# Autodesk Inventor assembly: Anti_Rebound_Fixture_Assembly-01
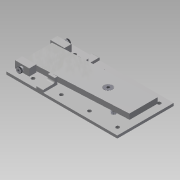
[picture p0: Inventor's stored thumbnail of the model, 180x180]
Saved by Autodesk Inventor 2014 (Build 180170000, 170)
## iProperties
Company: NHTSA/VRTC
Created: 2012-08
Part Number: Anti_Rebound_Fixture_Assembly-01
Document SubType Name: Weldment
Designer: Mike Vanvoorhis
Weld Material: Welded Steel Mild
Mass: 12341 g
Surface Area: 3135.86 cm^2
Volume: 1591.33 cm^3
Density: 7.75514 g/cm^3
Description: ANTI-REBOUND FIXTURE ASS'Y.
Project: CHILD SIDE IMPACT SLED
DESIGN DATE: 2012-11-05
Author: Dave Walker
Title: Anti-Rebound Fixture Assembly
Subject: Child Side Impact Sled
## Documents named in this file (12)
- B:\VRTC_DWG\BIO\Non-P572\Child Side-Frontal Impact Sled\Side Impact Sled\Anti_Rebound_Fixture_Assembly.iam
- B:\VRTC_DWG\BIO\Non-P572\Child Side-Frontal Impact Sled\Side Impact Sled\Anti_Rebound_Fixture_Base.ipt
- B:\VRTC_DWG\BIO\Non-P572\Child Side-Frontal Impact Sled\Side Impact Sled\Anti_Rebound_Fixture_Pivot.ipt
- B:\VRTC_DWG\BIO\Non-P572\Child Side-Frontal Impact Sled\Side Impact Sled\Anti_Rebound_Fixture_Stop.ipt
- B:\VRTC_DWG\BIO\Non-P572\Child Side-Frontal Impact Sled\Side Impact Sled\Anti_Rebound_Fixture_Shoulder Bolt.ipt
- B:\VRTC_DWG\BIO\Non-P572\Child Side-Frontal Impact Sled\Side Impact Sled\Anti_Rebound_Fixture_Guide.ipt
- B:\VRTC_DWG\BIO\Non-P572\Child Side-Frontal Impact Sled\Side Impact Sled\Anti_Rebound_Fixture_Spring.ipt
- B:\VRTC_DWG\BIO\Non-P572\Child Side-Frontal Impact Sled\Side Impact Sled\90630A130.ipt
- B:\VRTC_DWG\BIO\Non-P572\Child Side-Frontal Impact Sled\Side Impact Sled\Rubber_Washer.ipt
- B:\VRTC_DWG\Inventor Support Files\Content Center\en-US\ASTM F436(1)\ASTM F436 - 5_8(1).ipt
- B:\VRTC_DWG\Inventor Support Files\Content Center\en-US\ANSI B18.3(04)\ANSI B18.3 - 5_8-11 UNC - 3.5(30).ipt
- Anti_Rebound_Fixture_Assembly-01.iam
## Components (16 placed, 10 different names)
1. Anti_Rebound_Fixture_Base:1 — Flush:1, Flush:2, Flush:3, Flush:4, Mate:1, Flush:5, Flush:6, Flush:8, Insert:9, Flush:10, Flush:11, Flush:12, Insert:20, Insert:22, Insert:23
2. Anti_Rebound_Fixture_Pivot:1 — Flush:1, Insert:12, Insert:13, Flush:10, Flush:12
3. Anti_Rebound_Fixture_Pivot:2 — Flush:2, Flush:3, Mate:2, Flush:9, Flush:11
4. Anti_Rebound_Fixture_Stop:1 — Insert:12, Tangent:1, Mate:3, Mate:4
5. Anti_Rebound_Fixture_Shoulder Bolt:1 — Insert:13
6. Anti_Rebound_Fixture_Shoulder Bolt:2 — Mate:2, Flush:9
7. Anti_Rebound_Fixture_Guide:1 — Flush:4, Mate:1, Flush:7, Flush:8
8. Anti_Rebound_Fixture_Guide:2 — Flush:5, Flush:6, Flush:7
9. Anti_Rebound_Fixture_Spring:1 — Insert:22, Tangent:1
10. Anti_Rebound_Fixture_Spring:2 — Insert:9
11. Anti_Rebound_Fixture_Spring:3 — Insert:23
12. Anti_Rebound_Fixture_Spring:5 — Insert:20
13. 90630A130:1 — Insert:18
14. Rubber_Washer:1 — Insert:19, Insert:24
15. Socket Flat Countersunk Head Cap Screw - Inch 5/8-11 UNC x 3.5 — Mate:3, Mate:4, Insert:24
16. Circular Washer (Inch) 5/8:1 — Insert:18, Insert:19
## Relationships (26: Flush 12, Insert 9, Mate 4, Tangent 1)
- Flush:1: Anti_Rebound_Fixture_Base:1 ↔ Anti_Rebound_Fixture_Pivot:1
- Flush:2: Anti_Rebound_Fixture_Base:1 ↔ Anti_Rebound_Fixture_Pivot:2
- Flush:3: Anti_Rebound_Fixture_Base:1 ↔ Anti_Rebound_Fixture_Pivot:2
- Flush:4: Anti_Rebound_Fixture_Base:1 ↔ Anti_Rebound_Fixture_Guide:1
- Mate:1: Anti_Rebound_Fixture_Base:1 ↔ Anti_Rebound_Fixture_Guide:1
- Flush:5: Anti_Rebound_Fixture_Base:1 ↔ Anti_Rebound_Fixture_Guide:2
- Flush:6: Anti_Rebound_Fixture_Base:1 ↔ Anti_Rebound_Fixture_Guide:2
- Flush:7: Anti_Rebound_Fixture_Guide:1 ↔ Anti_Rebound_Fixture_Guide:2
- Flush:8: Anti_Rebound_Fixture_Base:1 ↔ Anti_Rebound_Fixture_Guide:1
- Insert:9: Anti_Rebound_Fixture_Base:1 ↔ Anti_Rebound_Fixture_Spring:2
- Insert:12: Anti_Rebound_Fixture_Pivot:1 ↔ Anti_Rebound_Fixture_Stop:1
- Insert:13: Anti_Rebound_Fixture_Pivot:1 ↔ Anti_Rebound_Fixture_Shoulder Bolt:1
- Mate:2: Anti_Rebound_Fixture_Pivot:2 ↔ Anti_Rebound_Fixture_Shoulder Bolt:2
- Flush:9: Anti_Rebound_Fixture_Pivot:2 ↔ Anti_Rebound_Fixture_Shoulder Bolt:2
- Flush:10: Anti_Rebound_Fixture_Base:1 ↔ Anti_Rebound_Fixture_Pivot:1
- Flush:11: Anti_Rebound_Fixture_Base:1 ↔ Anti_Rebound_Fixture_Pivot:2
- Flush:12: Anti_Rebound_Fixture_Base:1 ↔ Anti_Rebound_Fixture_Pivot:1
- Insert:18: 90630A130:1 ↔ Circular Washer (Inch) 5/8:1
- Insert:19: Rubber_Washer:1 ↔ Circular Washer (Inch) 5/8:1
- Insert:20: Anti_Rebound_Fixture_Base:1 ↔ Anti_Rebound_Fixture_Spring:5
- Insert:22: Anti_Rebound_Fixture_Base:1 ↔ Anti_Rebound_Fixture_Spring:1
- Insert:23: Anti_Rebound_Fixture_Base:1 ↔ Anti_Rebound_Fixture_Spring:3
- Tangent:1: Anti_Rebound_Fixture_Stop:1 ↔ Anti_Rebound_Fixture_Spring:1
- Mate:3: Anti_Rebound_Fixture_Stop:1 ↔ Socket Flat Countersunk Head Cap Screw - Inch 5/8-11 UNC x 3.5
- Mate:4: Anti_Rebound_Fixture_Stop:1 ↔ Socket Flat Countersunk Head Cap Screw - Inch 5/8-11 UNC x 3.5
- Insert:24: Rubber_Washer:1 ↔ Socket Flat Countersunk Head Cap Screw - Inch 5/8-11 UNC x 3.5
